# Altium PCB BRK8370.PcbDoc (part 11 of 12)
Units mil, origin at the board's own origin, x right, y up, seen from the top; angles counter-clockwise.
Board outline 8267.72 x 5708.66 mil, 6 copper layers (L1-TOP, L2-GND, L3-PWR, L4-PWR, L5-GND, L6-BOT), stack 68.606 mil thick; 319 components, 516 nets, 2008 pads, 1743 vias.
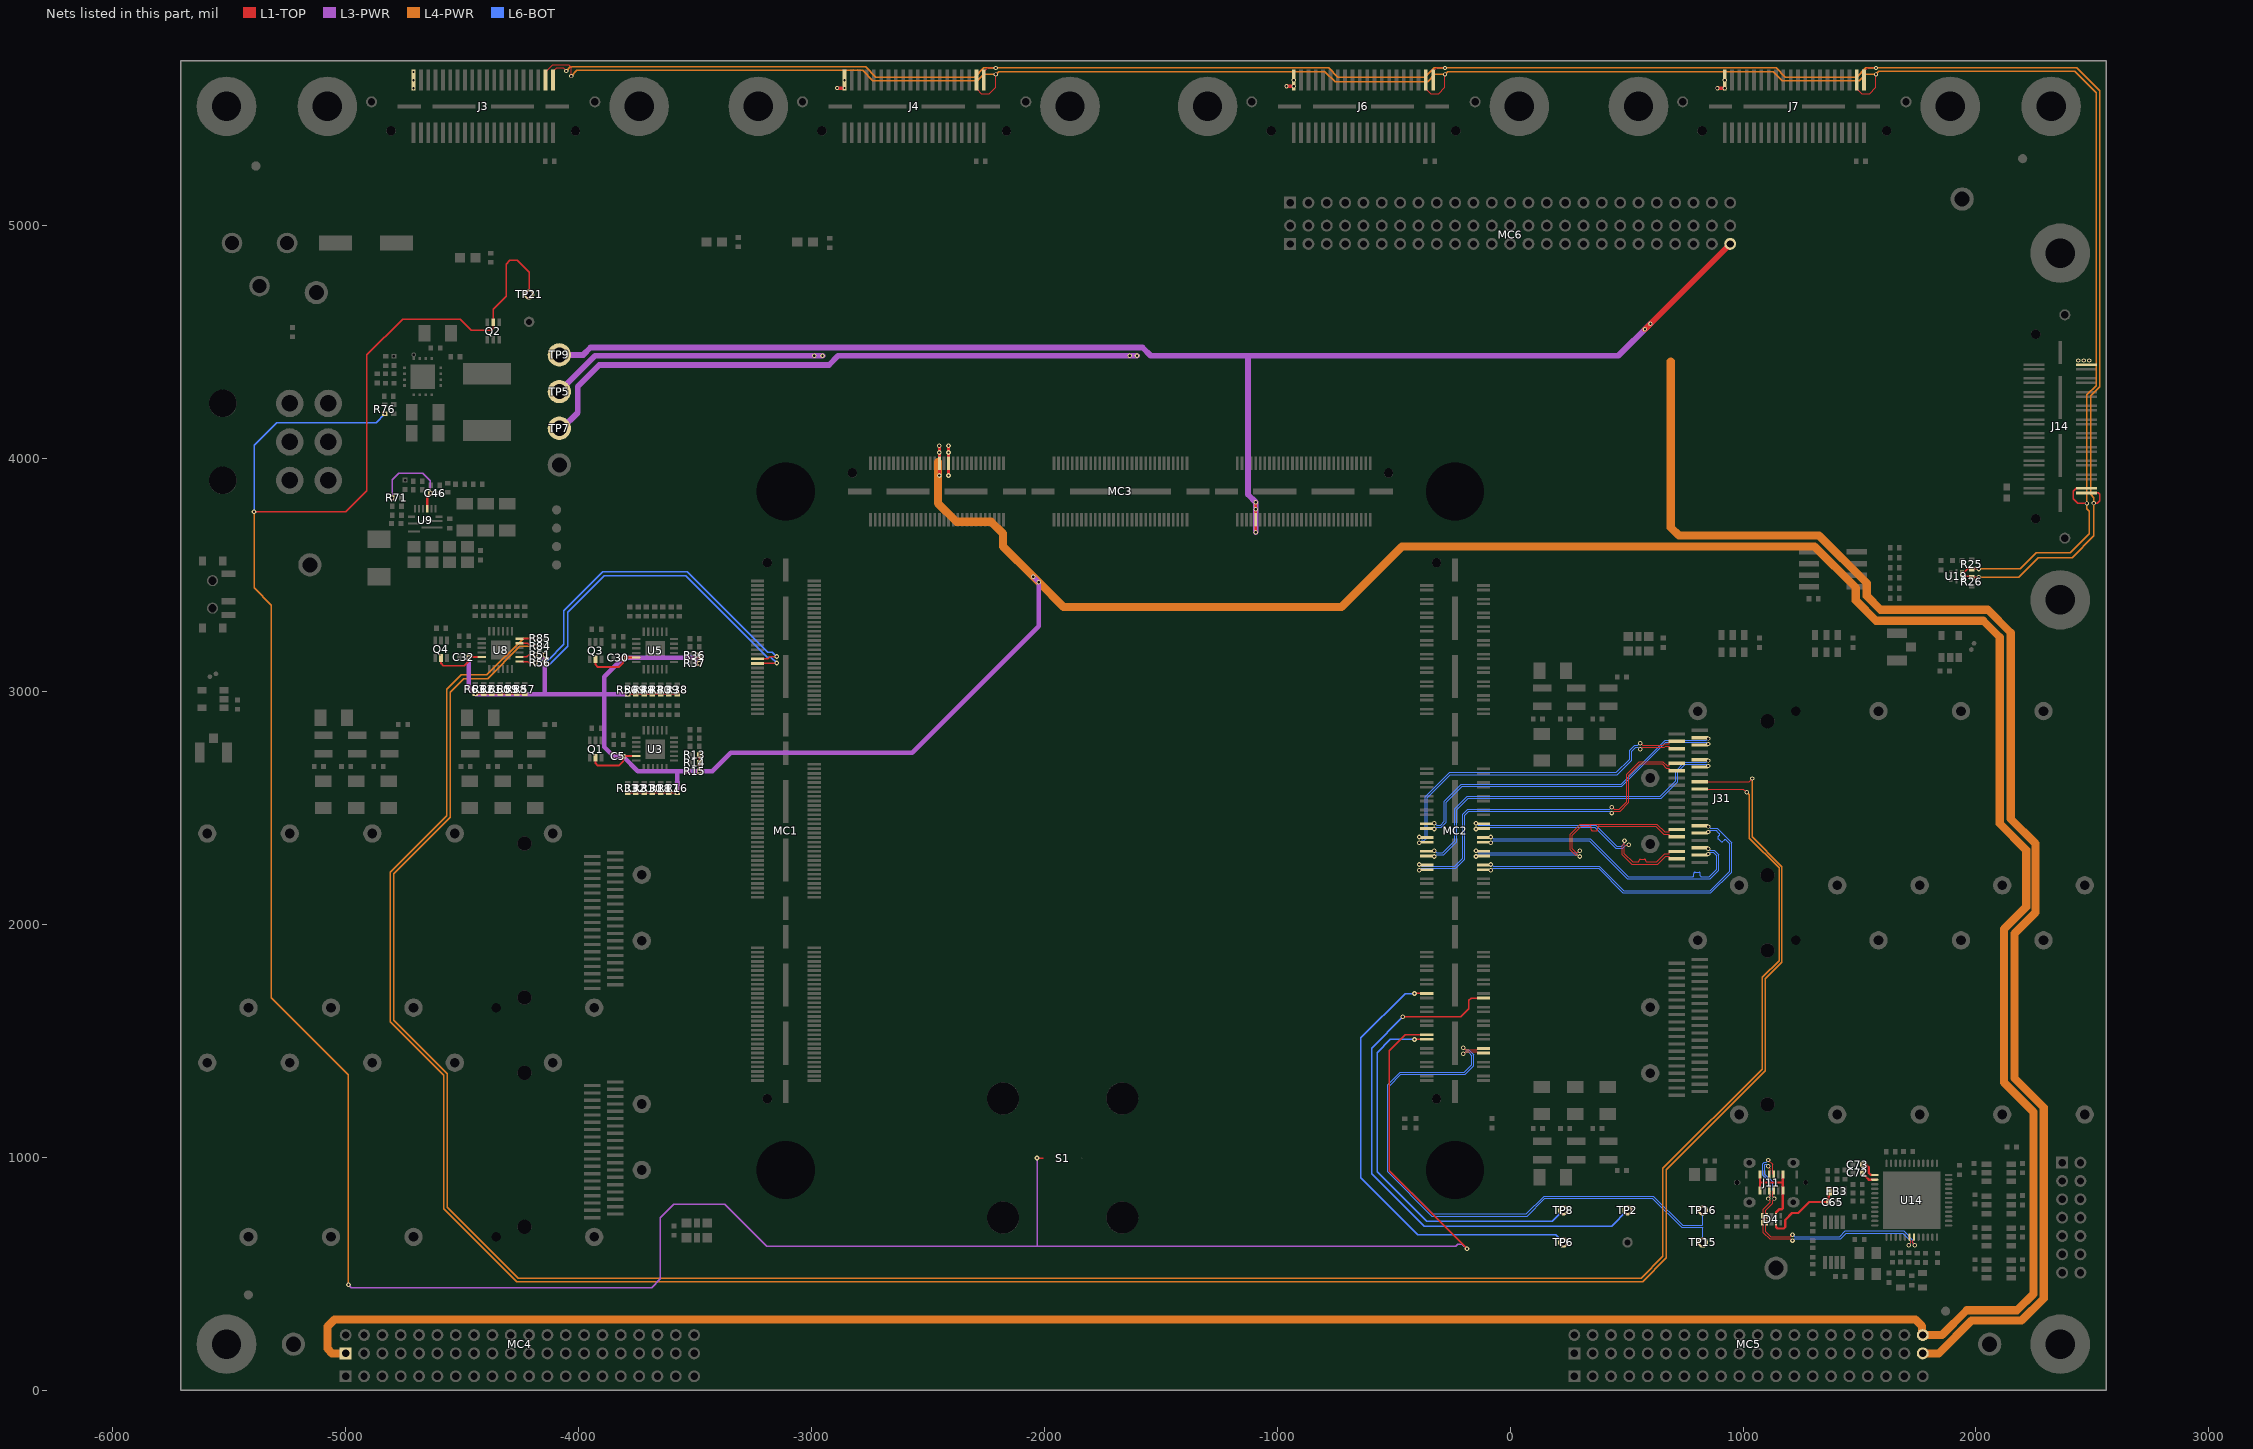
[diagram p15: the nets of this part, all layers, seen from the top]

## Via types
v1: diameter 20, hole 10, L1-TOP to L6-BOT, tented both sides, 957 vias
v2: diameter 18, hole 10, L1-TOP to L6-BOT, tented both sides, 786 vias

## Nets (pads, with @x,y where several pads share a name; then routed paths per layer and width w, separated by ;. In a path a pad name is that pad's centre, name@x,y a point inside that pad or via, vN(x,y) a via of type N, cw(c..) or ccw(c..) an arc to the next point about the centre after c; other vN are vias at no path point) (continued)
QSFP_4_RX1_N: J31.18 MC2.63 | length 1383.8
  L6-BOT w3.3: v1(-325.98,2433.76) -323.7,2433.76 -315.7,2425.76 -298.75,2425.76 -282.34,2442.17 -282.34,2528 -209.66,2600.68 -61.42,2600.68 476.12,2600.68 665.38,2789.93 841.14,2789.93 848.29,2797.08 v2(850.43,2797.08)
QSFP_4_RX1_P: J31.17 MC2.61 | length 1383.8
  L6-BOT w3.3: v1(-325.98,2408.76) -323.7,2408.76 -315.7,2416.76 -295.02,2416.76 -273.34,2438.44 -273.34,2524.27 -205.93,2591.68 -61.42,2591.68 479.85,2591.68 669.11,2780.93 841.14,2780.93 848.29,2773.79 v2(850.43,2773.79)
QSFP_4_RX2_N: J31.21 MC2.59 | length 1414.4
  L1-TOP w3.3: v1(559.06,2776.97) 561.34,2776.97 569.34,2768.97 658.19,2768.97 663.41,2774.18 680.43,2774.18 682.36,2776.12 682.36,2780.19 687.6,2785.43 J31.21@716.14,2785.43
  L6-BOT w3.3: v1(-389.76,2374.7) -387.48,2374.7 -379.48,2366.7 -374.22,2366.7 -365.02,2375.91 -365.02,2546.94 -260.1,2651.86 -61.42,2651.86 456.6,2651.86 512.94,2708.2 512.94,2746.73 535.18,2768.97 548.77,2768.97 556.77,2776.97 v1(559.06,2776.97)
QSFP_4_RX2_P: J31.22 MC2.57 | length 1414.4
  L1-TOP w3.3: v1(559.06,2751.97) 561.34,2751.97 569.34,2759.97 661.92,2759.97 667.14,2765.18 680.43,2765.18 682.36,2763.25 682.36,2759.18 687.6,2753.94 J31.22@716.14,2753.94
  L6-BOT w3.3: v1(-389.76,2349.7) -387.48,2349.7 -379.48,2357.7 -370.49,2357.7 -356.02,2372.18 -356.02,2543.21 -256.37,2642.86 -61.42,2642.86 460.33,2642.86 521.94,2704.47 521.94,2743 538.9,2759.97 548.77,2759.97 556.77,2751.97 v1(559.06,2751.97)
QSFP_4_RX3_N: J31.15 MC2.55 | length 1448.2
  L6-BOT w3.3: v1(-325.98,2315.65) -323.7,2315.65 -315.7,2307.65 -289.18,2307.65 -238.47,2358.36 -238.47,2495.6 -184.01,2550.06 -61.42,2550.06 644.41,2550.06 710.35,2616 710.35,2657.74 748.06,2695.44 841.14,2695.44 848.29,2702.59 v2(850.43,2702.59)
QSFP_4_RX3_P: J31.14 MC2.53 | length 1448.2
  L6-BOT w3.3: v1(-325.98,2290.65) -323.7,2290.65 -315.7,2298.65 -285.46,2298.65 -229.47,2354.63 -229.47,2491.87 -180.28,2541.06 -61.42,2541.06 648.13,2541.06 719.35,2612.27 719.35,2654.01 751.78,2686.44 841.14,2686.44 848.29,2679.3 v2(850.43,2679.3)
QSFP_4_RX4_N: J31.24 MC2.51 | length 1495.6
  L1-TOP w3.3: v1(437.01,2502.38) 439.29,2502.38 447.29,2494.38 468.41,2494.38 500.93,2526.9 500.93,2643.71 554.91,2697.69 656.14,2697.69 674.14,2679.7 680.43,2679.7 682.36,2681.63 682.36,2685.7 687.6,2690.94 J31.24@716.14,2690.94
  L6-BOT w3.3: v1(-389.76,2256.59) -387.48,2256.59 -379.48,2248.59 -238,2248.59 -203.6,2283 -203.6,2472.14 -181.36,2494.38 -61.42,2494.38 426.72,2494.38 434.72,2502.38 v1(437.01,2502.38)
QSFP_4_RX4_P: J31.25 MC2.49 | length 1495.6
  L1-TOP w3.3: v1(437.01,2477.38) 439.29,2477.38 447.29,2485.38 472.14,2485.38 509.93,2523.17 509.93,2639.98 558.64,2688.69 652.42,2688.69 670.41,2670.7 680.43,2670.7 682.36,2668.76 682.36,2664.69 687.6,2659.45 J31.25@716.14,2659.45
  L6-BOT w3.3: v1(-389.76,2231.59) -387.48,2231.59 -379.48,2239.59 -234.28,2239.59 -194.6,2279.27 -194.6,2468.41 -177.63,2485.38 -61.42,2485.38 426.72,2485.38 434.72,2477.38 v1(437.01,2477.38)
QSFP_4_SCL_3V3: J31.11 R84.1 U8.11 | length 10777.5
  L1-TOP w5: J31.11@814.96,2580.71 1001.97,2580.71 v2(1015.75,2566.93)
  L1-TOP w6: U8.11@-4253.94,3206.69 -4218.5,3206.69 -4204.72,3192.91 v1(-4185.04,3192.91)
  L4-PWR w6: v1(-4185.04,3192.91) -4251.97,3192.91 -4389.76,3055.12 -4492.13,3055.12 -4551.25,2995.99 -4551.25,2458.99 -4793.47,2216.78 -4793.47,1588.38 -4563.71,1358.62 -4563.71,785.27 -4259.09,480.64 563.32,480.64 656.19,573.51 656.19,951.56 1082.68,1378.05 1082.68,1771.7 1155.12,1844.15 1155.12,2242.52 1027.56,2370.08 1027.56,2555.12 v2(1015.75,2566.93)
QSFP_4_SCL_VIO: MC1.145 R51.1 U8.8 | length 1597.2
  L1-TOP w6: U8.8@-4253.94,3147.64 -4222.44,3147.64 -4212.6,3157.48 v1(-4185.04,3157.48) ; MC1.145@-3231.89,3139.76 -3187.01,3139.76 -3177.17,3149.61 v1(-3149.61,3149.61)
  L6-BOT w6: v1(-4185.04,3157.48) -4161.42,3133.86 -4130.95,3133.86 -4062.99,3201.81 -4062.99,3347.08 -3897.06,3513.01 -3532.7,3513.01 -3188.35,3168.66 -3168.66,3168.66 v1(-3149.61,3149.61)
QSFP_4_SDA_3V3: J31.12 R85.1 U8.12 | length 10936
  L1-TOP w5: J31.12@814.96,2612.2 1026.28,2612.2 1039.37,2625.3 v2(1039.37,2625.98)
  L1-TOP w6: U8.12@-4253.94,3226.38 -4187.01,3226.38 v1(-4185.04,3228.35)
  L4-PWR w6: v1(-4185.04,3228.35) -4236.22,3228.35 -4393.7,3070.87 -4503.54,3070.87 -4566.28,3008.13 -4566.28,2465.22 -4808.49,2223 -4808.49,1582.15 -4578.74,1352.4 -4578.74,779.04 -4265.31,465.61 569.54,465.61 671.21,567.28 671.21,945.67 1096.48,1370.93 1096.48,1766.25 1166.93,1836.7 1166.93,2247.41 1039.37,2374.97 v2(1039.37,2625.98)
QSFP_4_SDA_VIO: MC1.143 R56.1 U8.7 | length 1597
  L1-TOP w6: U8.7@-4253.94,3127.95 -4218.5,3127.95 -4212.6,3122.05 v1(-4185.04,3122.05) ; MC1.143@-3231.89,3120.08 -3230.91,3121.06 -3150.59,3121.06 v1(-3149.61,3122.05)
  L6-BOT w6: v1(-4185.04,3122.05) -4173.23,3110.24 -4129.92,3110.24 -4047.24,3192.91 -4047.24,3340.56 -3890.54,3497.27 -3539.22,3497.27 -3188.96,3147.01 -3174.57,3147.01 v1(-3149.61,3122.05)
QSFP_4_TX1_N: J31.37 MC2.64 | length 1030.6
  L1-TOP w3.3: v1(491.12,2359.27) 489.51,2357.66 489.51,2346.35 482,2338.84 482,2298.96 522.23,2258.73 633.12,2258.73 667.14,2292.74 680.43,2292.74 682.36,2290.81 682.36,2286.74 687.6,2281.5 J31.37@716.14,2281.5
  L6-BOT w3.3: v1(-146.46,2433.76) -144.17,2433.76 -136.17,2425.76 -61.42,2425.76 368.09,2425.76 458.09,2335.75 478.91,2335.75 489.51,2346.35 489.51,2357.66 v1(491.12,2359.27)
QSFP_4_TX1_P: J31.36 MC2.62 | length 1030.6
  L1-TOP w3.3: v1(508.8,2341.6) 507.18,2339.98 495.87,2339.98 491,2335.11 491,2302.68 525.95,2267.73 533.62,2267.73 548.25,2267.73 ccw(c548.25,2273.39) 553.91,2273.39 553.91,2274.38 cw(c559.57,2274.38) 559.57,2280.04 576.55,2280.04 cw(c576.55,2274.38) 582.21,2274.38 582.21,2273.39 ccw(c587.87,2273.39) 587.87,2267.73 617.82,2267.73 629.39,2267.73 663.41,2301.74 680.43,2301.74 682.36,2303.68 682.36,2307.75 687.6,2312.99 J31.36@716.14,2312.99
  L6-BOT w3.3: v1(-146.46,2408.76) -144.17,2408.76 -136.17,2416.76 -61.42,2416.76 364.36,2416.76 454.37,2326.75 482.64,2326.75 495.87,2339.98 507.18,2339.98 v1(508.8,2341.6)
QSFP_4_TX2_N: J31.2 MC2.60 | length 1187.5
  L6-BOT w3.3: v1(-82.68,2374.7) -80.39,2374.7 -72.39,2366.7 -61.42,2366.7 344.3,2366.7 507.41,2203.6 781.37,2203.6 783.02,2203.6 ccw(c783.02,2209.26) 788.68,2209.26 788.68,2217.71 cw(c794.34,2217.71) 794.34,2223.37 811.32,2223.37 cw(c811.32,2217.71) 816.98,2217.71 816.98,2209.26 ccw(c822.64,2209.26) 822.64,2203.6 842.52,2203.6 854.8,2203.6 886.95,2235.75 886.95,2294.15 872.61,2308.49 859.71,2308.49 852.56,2301.35 v2(850.43,2301.35)
QSFP_4_TX2_P: J31.3 MC2.58 | length 1187.5
  L6-BOT w3.3: v1(-82.68,2349.7) -80.39,2349.7 -72.39,2357.7 -61.42,2357.7 340.57,2357.7 503.68,2194.6 858.52,2194.6 895.95,2232.03 895.95,2297.88 876.34,2317.49 859.71,2317.49 852.56,2324.64 v2(850.43,2324.64)
QSFP_4_TX3_N: J31.34 MC2.56 | length 1069.3
  L1-TOP w3.3: v1(299.21,2315.65) 296.93,2315.65 288.93,2307.65 283.67,2307.65 266.59,2324.72 266.59,2382.36 305.21,2420.98 312.57,2420.98 342.52,2420.98 cw(c342.52,2415.32) 348.18,2415.32 348.18,2406.87 ccw(c353.84,2406.87) 353.84,2401.21 370.82,2401.21 ccw(c370.82,2406.87) 376.48,2406.87 376.48,2415.32 cw(c382.14,2415.32) 382.14,2420.98 429.8,2420.98 625.73,2420.98 659.47,2387.23 680.43,2387.23 682.36,2385.3 682.36,2381.22 687.6,2375.98 J31.34@716.14,2375.98
  L6-BOT w3.3: v1(-146.46,2315.65) -144.17,2315.65 -136.17,2307.65 -61.42,2307.65 288.93,2307.65 296.93,2315.65 v1(299.21,2315.65)
QSFP_4_TX3_P: J31.33 MC2.54 | length 1069.3
  L1-TOP w3.3: v1(299.21,2290.65) 296.93,2290.65 288.93,2298.65 279.94,2298.65 257.59,2321 257.59,2386.08 301.49,2429.98 629.45,2429.98 663.2,2396.23 680.43,2396.23 682.36,2398.17 682.36,2402.24 687.6,2407.48 J31.33@716.14,2407.48
  L6-BOT w3.3: v1(-146.46,2290.65) -144.17,2290.65 -136.17,2298.65 -61.42,2298.65 288.93,2298.65 296.93,2290.65 v1(299.21,2290.65)
QSFP_4_TX4_N: J31.5 MC2.52 | length 1371.9
  L6-BOT w3.3: v1(-82.68,2256.59) -80.39,2256.59 -72.39,2248.59 -61.42,2248.59 383.67,2248.59 487.72,2144.54 858.73,2144.54 942.07,2227.88 942.07,2346.2 928.1,2360.17 926.93,2361.34 ccw(c922.93,2357.34) 918.93,2361.34 912.95,2355.36 cw(c908.95,2359.37) 904.95,2355.36 892.94,2367.37 cw(c896.94,2371.37) 892.94,2375.37 898.92,2381.35 ccw(c894.91,2385.35) 898.92,2389.35 890.06,2398.21 885.29,2402.98 859.71,2402.98 852.56,2395.83 v2(850.43,2395.83)
QSFP_4_TX4_P: J31.6 MC2.50 | length 1371.9
  L6-BOT w3.3: v1(-82.68,2231.59) -80.39,2231.59 -72.39,2239.59 -61.42,2239.59 379.94,2239.59 484,2135.54 862.46,2135.54 951.07,2224.15 951.07,2349.93 889.02,2411.98 859.71,2411.98 852.56,2419.13 v2(850.43,2419.13)
RT6278_VCC: C46.2 R71.2 U9.9 | length 391.9
  L1-TOP w9: U9.9@-4649.76,3784.66 -4649.76,3836.64 v1(-4636.03,3850.36)
  L3-PWR w6: v1(-4799.88,3830.94) -4799.88,3908.78 -4771.65,3937.01 -4669.29,3937.01 -4636.03,3903.75 v1(-4636.03,3850.36)
SZG_SCL_3V3: J3.1 J4.1 J6.1 J7.1 J14.1@2475.2,3851.92 R26.1 U19.6 | length 9809.9
  L1-TOP w5: J3.1@-4110.2,5624.61 -4110.2,5661.36 -4094.54,5677.02 -4066.39,5677.02 v2(-4052.88,5663.52) ; J4.1@-2259.81,5624.61 -2259.81,5661.36 -2244.14,5677.02 v2(-2208.86,5677.02) ; J6.1@-330.62,5624.61 -330.67,5661.36 -315.01,5677.02 v2(-279.72,5677.02) ; J7.1@1519.72,5624.61 1519.72,5661.36 1535.38,5677.02 v2(1570.67,5677.02)
  L1-TOP w6: U19.6@1940.16,3494.09 1979.13,3494.09 R26.1@1983.07,3490.16 v1(2011.81,3490.16) ; J14.1@2475.2,3851.92 2526.03,3851.92 2531.5,3846.46 2531.5,3818.9 2520.81,3808.22 v2(2506.3,3808.22)
  L4-PWR w6: v2(-4052.88,5663.52) -4035.3,5681.1 -2767.72,5681.1 -2724.41,5637.8 -2299.21,5637.8 -2259.99,5677.02 v2(-2208.86,5677.02) -779.38,5677.02 -740.16,5637.8 -366.14,5637.8 -326.92,5677.02 v2(-279.72,5677.02) 1141.88,5677.02 1181.1,5637.8 1488.19,5637.8 1527.42,5677.02 v2(1570.67,5677.02) 2433.64,5677.02 2531.5,5579.16 2531.5,4307.09 2493.22,4268.81 2493.22,3845.36 2506.3,3832.28 v2(2506.3,3808.22) 2506.3,3667.72 2413.39,3574.8 2267.72,3574.8 2183.07,3490.16 v1(2011.81,3490.16)
SZG_SDA_3V3: J3.3 J4.3 J6.3 J7.3 J14.3 R25.1 U19.7 | length 10176.8
  L1-TOP w4.4: J3.3@-4141.65,5624.61 -4141.65,5661.36 -4111.55,5691.46 -4041.86,5691.46 -4031.5,5681.1 v2(-4031.5,5641.73)
  L1-TOP w5: J4.3@-2291.31,5624.61 -2291.31,5587.86 -2270.37,5566.93 -2236.27,5566.93 -2208.86,5594.34 v2(-2208.86,5649.46) ; J6.3@-362.12,5624.61 -362.17,5587.86 -341.24,5566.93 -307.14,5566.93 -279.72,5594.34 v2(-279.72,5649.46) ; J7.3@1488.22,5624.61 1488.22,5587.86 1509.15,5566.93 1543.26,5566.93 1570.67,5594.34 v2(1570.67,5649.46)
  L1-TOP w6: U19.7@1940.16,3513.78 1952.76,3513.78 1964.57,3525.59 R25.1@1983.07,3525.59 v1(2011.81,3525.59) ; J14.3@2475.2,3871.6 2430.51,3871.6 2417.32,3858.41 2417.32,3826.77 2437.01,3807.09 v2(2476.38,3807.09)
  L4-PWR w6: v2(-4031.5,5641.73) -4007.23,5666 -2780.17,5666 -2736.22,5622.05 -2287.4,5622.05 -2259.99,5649.46 v2(-2208.86,5649.46) -2196.9,5661.42 -795.28,5661.42 -751.97,5618.11 -354.33,5618.11 -322.98,5649.46 v2(-279.72,5649.46) -267.77,5661.42 1129.92,5661.42 1169.29,5622.05 1500,5622.05 1527.42,5649.46 v2(1570.67,5649.46) 1583.72,5662.51 2424.53,5662.51 2515.75,5571.29 2515.75,4313.2 2476.38,4273.83 v2(2476.38,3807.09) 2476.38,3794.99 2476.38,3783.46 2487,3772.85 2487,3675.97 2405.51,3594.49 2259.84,3594.49 2190.95,3525.59 v1(2011.81,3525.59)
USB_DN: D4.5 D4.6 J11.A7 J11.B7 U14.6 | length 1213.9
  L1-TOP w4: v2(1108.73,987.57) 1127.05,969.25 1127.05,942.47 1127.98,941.53 1127.98,928.91 J11.B7@1131.89,925 ; J11.A7@1112.2,856.89 1116.11,852.98 1116.11,840.36 1117.05,839.42 1117.05,831.34 1109.39,823.68 1108.73,823.68 1108.73,820.66 1116.73,812.66 1116.73,806.35 1087.52,777.14 1087.52,760.94 1082.68,756.1 1082.68,741.34 1087.5,736.51 1087.52,730.42 1082.68,725.59 1082.68,710.83 1087.52,705.98 1087.52,676.18 1114.47,649.23 1202.26,649.23 1209.76,641.73 v1(1212.6,641.73) ; v1(1711.82,621.87) 1711.82,624.71 1719.41,632.3 1719.41,640.4 1714.57,645.25 U14.6@1714.57,656.5
  L6-BOT w4: v2(1108.73,822) 1108.73,823.34 1116.73,831.34 1116.73,889.48 1083.67,922.54 1083.67,970.87 1091.87,979.07 1099.38,979.07 1107.88,987.57 v2(1108.73,987.57) ; v1(1212.6,641.73) 1215.44,641.73 1222.94,649.23 1420.06,649.23 1444.16,673.33 1685.82,673.33 1719.32,639.83 1719.32,632.21 1711.82,624.71 v1(1711.82,621.87)
USB_DP: D4.4 D4.7 J11.A6 J11.B6 U14.7 | length 1165.4
  L1-TOP w4: v2(1108.73,960.57) 1108.73,959.54 1117.05,951.22 1117.05,942.47 1116.11,941.53 1116.11,928.91 J11.B6@1112.2,925 ; J11.A6@1131.89,856.89 1127.98,852.98 1127.98,840.36 1127.05,839.42 1127.05,831.34 1134.73,823.66 1134.73,820.66 1126.73,812.66 1126.73,802.21 1097.52,773 1097.52,760.94 1102.36,756.1 1102.36,741.34 1097.54,736.51 1097.52,730.42 1102.36,725.59 1102.36,710.83 1097.52,705.98 1097.52,680.32 1118.61,659.23 1202.26,659.23 1209.76,666.73 v1(1212.6,666.73) ; U14.7@1734.25,656.5 1734.25,645.25 1729.41,640.4 1729.41,632.21 1736.82,624.8 v1(1736.82,621.87)
  L6-BOT w4: v2(1108.73,960.57) 1107.88,960.57 1099.38,969.07 1096.01,969.07 1093.67,966.72 1093.67,926.68 1126.73,893.63 1126.73,831.34 1134.73,823.34 v2(1134.73,822) ; v1(1212.6,666.73) 1215.44,666.73 1222.94,659.23 1415.92,659.23 1440.01,683.33 1689.96,683.33 1729.32,643.97 1729.32,632.21 1736.82,624.71 v1(1736.82,621.87)
VBATT: MC2.13 TP8.1 | length 1654.9
  L1-TOP w6: v1(-410.77,1505.26) -410.44,1505.58 -358.2,1505.58 MC2.13@-357.87,1505.91
  L6-BOT w6: v1(-410.77,1505.26) -514.43,1505.26 -570.87,1448.82 -570.87,937.03 -358.75,724.92 181.61,724.92 TP8.1@228.35,771.65
VBUS_C: C65.2 D4.2 D4.9 FB3.2 J11.A4 J11.A9 J11.B4 J11.B9 | length 751.2
  L1-TOP w10: J11.A9@1072.83,856.89 1072.83,891.33 ; J11.B4@1072.83,925 1072.83,891.33 ; J11.B9@1171.26,925 1171.26,890.94 ; FB3.2@1370.87,854.33 1368.31,851.77 1368.31,809.65 C65.2@1365.75,807.09 1284.43,807.09 1237.18,759.84 1210.85,759.84 1181.24,730.23 1181.24,700.29 1174.45,693.5 1147.99,693.5 1141.73,699.76 D4.9@1141.73,718.21 1141.73,762.93 1154.39,775.59 1165.4,775.59 1171.26,781.45 J11.A4@1171.26,856.89 1171.26,890.94 ; 1072.83,891.33 1170.87,891.33 1171.26,890.94
VCCA: C73.2 U14.37 | length 85.9
  L1-TOP w10: C73.2@1512.2,967.52 1528.54,967.52 1539.37,956.69 1539.37,933.07 1549.21,923.23 U14.37@1565.94,923.23
VCCADC: MC2.26 TP2.1 | length 2348.2
  L1-TOP w6: v1(-460.63,1602.36) -212.6,1602.36 -177.17,1637.8 -177.17,1673.23 -167.32,1683.07 MC2.26@-114.57,1683.07
  L6-BOT w6: v1(-460.63,1602.36) -594.49,1468.5 -594.49,929.49 -369.28,704.28 436.57,704.28 TP2.1@503.94,771.65
VCCO_64_66: J6.39 J7.39 J14.39 MC3.35 MC5.39 TP7.1 | length 8867.5
  L1-TOP w12: v1(-2411.42,3927.17) MC3.35@-2411.42,3979.92 v1(-2411.42,4025.59) v1(-2411.42,4055.12)
  L1-TOP w15: v2(-960.63,5598.43) v2(-929.13,5598.43) ; v2(889.78,5589.61) v2(921.27,5589.61)
  L3-PWR w25: TP7.1@-4082.68,4129.92 -4070.87,4129.92 -4003.94,4196.85 -4003.94,4309 -3911.36,4401.57 -2925.2,4401.57 -2885.83,4440.94 v1(-1633.86,4440.94) v1(-1602.36,4440.94)
  L4-PWR w35: 689.56,4416.79 689.56,3704.14 724.41,3669.29 1326.65,3669.29 1531.5,3464.45 1531.5,3409.33 1590.44,3350.39 2051.07,3350.39 2149.61,3251.85 2149.61,2452.76 2255.91,2346.46 2255.91,2051.18 2165.35,1960.63 2165.35,1338.58 2291.31,1212.62 2291.31,393.74 2195.55,297.98 1980.77,297.98 1840.27,157.48 MC5.39@1771.65,157.48
  other v2: 2439.85,4420.86 2462.85,4420.86 2486.85,4420.86 -929.12,5624.61 921.27,5624.61
VCCO_67_68_69: C5.2 C30.2 C32.2 J3.39 J4.39 MC3.31 MC4.1 MC5.40 Q1.5 Q3.5 Q4.5 R13.2 R14.2 R15.2 R16.2 R17.2 R18.2 R30.2 R31.2 R32.2 R33.2 R36.2 R37.2 R38.2 R39.2 R40.2 R41.2 R48.2 R49.2 R50.2 R51.2 R56.2 R57.2 R58.2 R59.2 R60.2 R61.2 R62.2 R63.2 TP5.1 U3.23 U5.23 U8.23 | length 22910
  L1-TOP w6: v1(-4442.91,2990.16) R62.2@-4407.48,2990.16 R61.2@-4372.05,2990.16 R60.2@-4336.61,2990.16 R59.2@-4301.18,2990.16 R58.2@-4265.75,2990.16 R57.2@-4230.31,2990.16 ; R56.2@-4145.67,3122.05 v1(-4145.67,3157.48) ; R33.2@-3789.37,2564.96 R32.2@-3753.94,2564.96 R31.2@-3718.5,2564.96 R30.2@-3683.07,2564.96 R18.2@-3647.64,2564.96 R17.2@-3612.2,2564.96 v1(-3576.77,2564.96) ; v1(-3789.37,2988.19) R49.2@-3753.94,2988.19 R48.2@-3718.5,2988.19 R41.2@-3683.07,2988.19 R40.2@-3647.64,2988.19 R39.2@-3612.2,2988.19 R38.2@-3576.77,2988.19 ; v1(-3482.28,2657.48) R14.2@-3482.28,2692.91 R13.2@-3482.28,2728.35 ; v1(-3482.28,3120.08) R36.2@-3482.28,3155.51
  L1-TOP w8: Q4.5@-4590.55,3143.7 -4590.55,3120.08 -4580.71,3110.24 -4490.16,3110.24 -4472.05,3128.35 v1(-4472.05,3145.67) ; C32.2@-4472.05,3149.61 v1(-4472.05,3145.67) ; U8.23@-4415.35,3147.64 -4416.08,3146.91 -4470.8,3146.91 v1(-4472.05,3145.67) ; Q1.5@-3927.17,2714.57 -3927.17,2690.94 -3917.32,2681.1 -3826.77,2681.1 -3808.66,2699.21 v1(-3808.66,2720.47) -3807.42,2721.72 -3752.69,2721.72 U3.23@-3751.97,2722.44 ; Q3.5@-3927.17,3137.8 -3927.17,3114.17 -3917.32,3104.33 -3826.77,3104.33 -3808.66,3122.44 v1(-3808.66,3143.7) -3807.42,3144.94 -3752.69,3144.94 U5.23@-3751.97,3145.67
  L1-TOP w12: v1(-2450.79,3927.17) MC3.31@-2450.79,3979.92 v1(-2450.79,4025.59) v1(-2450.79,4055.12)
  L1-TOP w15: v2(-2889.76,5590.55) v2(-2858.27,5590.55)
  L3-PWR w20: v1(-4472.05,3145.67) -4472.05,3019.29 v1(-4442.91,2990.16) -4440.94,2988.19 -4145.67,2988.19 ; v1(-4145.67,3157.48) -4145.67,2988.19 ; v1(-3789.37,2988.19) -3889.76,2988.19 ; v1(-3576.77,2564.96) -3576.77,2655.51 -3574.8,2657.48 ; v1(-3482.28,3120.08) -3505.91,3143.7 v1(-3808.66,3143.7) -3889.76,3062.6 -3889.76,2988.19 ; v1(-2047.24,3492.13) v1(-2023.62,3468.5) -2023.62,3279.43 -2566.83,2736.22 -3346.46,2736.22 -3425.2,2657.48 v1(-3482.28,2657.48) -3574.8,2657.48 ; -4145.67,2988.19 -3889.76,2988.19 ; -3889.76,2988.19 -3889.76,2761.26 -3848.98,2720.47 v1(-3808.66,2720.47) -3745.67,2657.48 -3574.8,2657.48
  L3-PWR w25: TP5.1@-4082.68,4287.4 -3929.13,4440.94 v1(-2988.19,4440.94) v1(-2952.76,4440.94)
  L4-PWR w35: MC4.1@-5000,157.48 -5058.24,157.48 -5078.74,177.98 -5078.74,272.48 -5048.79,302.43 1740.88,302.43 1769.15,274.16 1769.15,238.72 MC5.40@1771.65,236.22 1854.3,236.22 1960.6,342.52 2177.1,342.52 2246.77,412.19 2246.77,1194.17 2120.81,1320.13 2120.81,1979.08 2215.91,2074.17 2215.91,2319.53 2102.36,2433.07 2102.36,3232.28 2031.5,3303.15 1570.87,3303.15 1484.25,3389.76 1484.25,3444.88 1306.32,3622.81 -463.8,3622.81 -724.41,3362.2 -1917.32,3362.2 v1(-2023.62,3468.5) v1(-2047.24,3492.13) -2177.17,3622.05 -2177.17,3677.17 -2228.35,3728.35 -2377.72,3728.35 -2456.92,3807.54 -2456.92,3984.25
  other v2: -4708.65,5589.61 -4708.65,5624.61 -2858.26,5624.61 -4708.65,5659.61
VCCO_88_89: MC3.130 MC6.49 TP9.1 | length 6186.5
  L1-TOP w12: v1(-1092.52,3683.86) MC3.130@-1092.52,3736.61 v1(-1092.52,3782.28) v1(-1092.52,3811.81)
  L1-TOP w25: v1(578.74,4555.12) v1(602.36,4578.74) MC6.49@944.88,4921.26
  L3-PWR w25: TP9.1@-4082.68,4444.88 -3980.31,4444.88 -3948.82,4476.38 -1578.74,4476.38 -1543.31,4440.94 -1125.98,4440.94 ; v1(-1092.52,3683.86) v1(-1092.52,3782.28) v1(-1092.52,3811.81) -1125.98,3845.28 -1125.98,4440.94 ; v1(602.36,4578.74) 464.57,4440.94 -1125.98,4440.94
VCORE: C72.2 U14.38 | length 65.9
  L1-TOP w10: C72.2@1512.2,932.09 1512.2,931.5 1540.16,903.54 U14.38@1565.94,903.54
VREFP: MC2.27 TP6.1 | length 1948.7
  L1-TOP w6: v1(-410.44,1702.43) -410.12,1702.76 MC2.27@-357.87,1702.76 MC2.27@-357.55,1703.08
  L6-BOT w6: v1(-410.44,1702.43) -451.11,1702.43 -641.31,1512.23 -641.31,910.62 -396.65,665.96 196.24,665.96 TP6.1@228.35,633.86
XADC_VN_C: MC2.12 TP16.1 | length 2527
  L1-TOP w3.3: v1(-200.79,1469.19) -198.5,1469.19 -190.5,1461.19 -142.55,1461.19 -137.2,1466.54 MC2.12@-114.57,1466.54
  L6-BOT w3.3: v1(-200.79,1469.19) -198.5,1469.19 -190.5,1461.19 -177.08,1461.19 -155.23,1439.34 -155.23,1393.44 -193.22,1355.46 -433.07,1355.46 -468.97,1355.46 -516.87,1307.55 -516.87,940.48 -332.61,756.22 68.83,756.22 145.57,832.96 614.43,832.96 740.13,707.26 824.84,707.26 826.77,709.19 TP16.1@826.77,771.65
XADC_VP_C: MC2.10 TP15.1 | length 2527
  L1-TOP w3.3: v1(-200.79,1444.19) -198.5,1444.19 -190.5,1452.19 -142.55,1452.19 -137.2,1446.85 MC2.10@-114.57,1446.85
  L6-BOT w3.3: v1(-200.79,1444.19) -198.5,1444.19 -190.5,1452.19 -180.81,1452.19 -164.23,1435.61 -164.23,1397.17 -196.95,1364.46 -433.07,1364.46 -472.7,1364.46 -525.87,1311.28 -525.87,936.75 -336.34,747.22 72.56,747.22 149.3,823.96 610.7,823.96 736.41,698.26 824.84,698.26 826.77,696.32 TP15.1@826.77,633.86
XEM8370_PGOOD: MC2.15 Q2.2 R76.2 S1.1 TP21.1 | length 13426.8
  L1-TOP w6: v1(-5393.7,3771.65) -5000,3771.65 -4909.45,3862.2 -4909.45,4444.88 -4755.91,4598.43 -4507.87,4598.43 -4460.63,4551.18 -4374.02,4551.18 -4366.14,4559.06 Q2.2@-4366.14,4584.65 -4366.14,4641.73 -4311.02,4696.85 -4311.02,4834.65 -4295.28,4850.39 -4263.78,4850.39 -4212.6,4799.21 TP21.1@-4212.6,4704.72 ; v1(-2031.5,996.06) S1.1@-2003.94,996.06 ; MC2.15@-357.87,1525.59 -451.07,1525.59 -519.68,1456.98 -519.68,940.94 v1(-185.04,606.3)
  L3-PWR w6: v1(-4988.19,452.76) -4975.57,440.13 -3685.66,440.13 -3648.8,477 -3648.8,740.06 -3590.91,797.95 -3372.94,797.95 -3192.29,617.3 -2031.5,617.3 ; v1(-2031.5,996.06) -2031.5,617.3 ; v1(-185.04,606.3) -204.72,625.98 -224.41,625.98 -233.09,617.3 -2031.5,617.3
  L4-PWR w6: v1(-5393.7,3771.65) -5393.7,3444.88 -5318.9,3370.08 -5318.9,3251.97 -5318.9,1683.69 -4988.19,1352.98 v1(-4988.19,452.76)
  L6-BOT w6: v1(-5393.7,3771.65) -5393.7,4056.99 -5296.55,4154.15 -4869.47,4154.15 v1(-4831.42,4192.2)
pads on no net: FID1.FID? FID2.FID? FID3.FID? FID4.FID? J1.3 J2.0 J3.37 J3.38 J3.MH J3.NC J4.37 J4.38 J4.MH J4.NC J5.12 J5.14 J6.37 J6.38 J6.MH J6.NC J7.37 J7.38 J7.MH J7.NC J8.MH J9.MH J11.A8 J11.B8 J11.M5 J11.M6 J14.1@2362.2,3392.91 J14.1@2362.2,4881.89 J14.37 J14.38 J14.MH J30.MH J31.MH JP3.0 JP3.1 JSO1.1 JSO2.1 JSO3.1 JSO4.1 MC1.55 MC1.56 MC1.159 MC1.MH MC2.9 MC2.11 MC2.19 MC2.23 MC2.25 MC2.69 MC2.70 MC2.71 MC2.72 MC2.73 MC2.74 MC2.75 MC2.76 MC2.77 MC2.78 MC2.79 MC2.80 MC2.81 MC2.82 MC2.83 MC2.84 MC2.85 MC2.86 MC2.87 MC2.88 MC2.89 MC2.90 MC2.91 MC2.92 MC2.93 MC2.94 MC2.95 MC2.96 MC2.97 MC2.98 MC2.99 MC2.100 MC2.117 MC2.119 MC2.MH MC3.30 MC3.32 MC3.132 MC3.133 MC3.135 MC3.MH MH1.1 MH2.1 MH3.1 MH4.1 QSFP1.0 QSFP2.0 QSFP3.0 QSFP4.0 S1.0 U1.2 U3.0 U4.2 U5.0 U5.9 U5.10 U6.2 U7.2 U8.0 U8.9 U8.10 U14.17 U14.18 U14.19 U14.20 U14.21 U14.25 U14.26 U14.27 U14.28 U14.29 U14.30 U14.31 U14.32 U14.33 U18.6 U18.7
copper on no net:
  other v2: -2185.09,5629.92 -255.96,5629.92 1594.44,5629.92

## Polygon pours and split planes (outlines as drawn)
NetC92_2 on L1-TOP "NETC92_2_L01_P597" (solid, pour order 597): 99.2,1052.27 177.94,1052.27 191.72,1066.05 191.72,1192.03 172.03,1211.72 101.17,1211.72 101.17,1155.61 114.94,1141.83 114.94,1107.39 99.2,1091.64
NetC90_2 on L1-TOP "NETC90_2_L01_P598" (solid, pour order 598): 243.88,1052.27 320.65,1052.27 334.43,1066.05 334.43,1192.03 314.75,1211.72 243.88,1211.72 243.88,1155.61 243.88,1093.61
NetC94_2 on L1-TOP "NETC94_2_L01_P599" (solid, pour order 599): 382.66,1052.27 459.43,1052.27 473.21,1066.05 473.21,1192.03 453.53,1211.72 382.66,1211.72 382.66,1155.61 382.66,1093.61
+3.3V_TST on L1-TOP "+3.3V_TST_L01_P600" (solid, pour order 600): 99.2,1020.77 461.4,1020.77 461.4,972.54 475.18,958.76 475.18,898.72 446.64,870.18 197.62,870.18 181.87,885.93 181.87,934.16 157.27,958.76 112.98,958.76 99.2,972.54
+VDCIN on L1-TOP "+VDCIN_L01_P607" (solid, pour order 607): -5283.46,4996.06 -4956.69,4996.06 -4940.94,4980.32 -4940.94,4515.75 -5157.48,4299.21 -5157.48,3834.65 -5181.1,3811.02 -5358.27,3811.02 -5409.45,3862.2 -5409.45,4570.87 -5311.02,4669.29 -5311.02,4968.5
DGND on L1-TOP "DGND_L01_P606" (solid, pour order 606): -4862.2,4984.25 -4862.2,4862.21 -4846.46,4846.46 -4677.17,4846.46 -4661.42,4862.2 -4661.42,4988.19 -4673.23,5000 -4846.46,5000
+VDCIN on L1-TOP "+VDCIN_L01_P605" (solid, pour order 605): -31.5,1417.32 -3.94,1389.76 -3.94,1188.98 -43.31,1149.61 -464.57,1149.61 -484.25,1169.29 -484.25,1393.7 -460.63,1417.32
NetC102_2 on L1-TOP "NETC102_2_L01_P603" (solid, pour order 603): 382.66,2951.67 459.43,2951.67 473.21,2937.89 473.21,2811.91 453.53,2792.22 382.66,2792.22 382.66,2848.32 382.66,2910.33
NetC106_2 on L1-TOP "NETC106_2_L01_P602" (solid, pour order 602): 243.88,2951.67 320.65,2951.67 334.43,2937.89 334.43,2811.91 314.75,2792.22 243.88,2792.22 243.88,2848.32 243.88,2910.33
NetC104_2 on L1-TOP "NETC104_2_L01_P601" (solid, pour order 601): 99.2,2951.67 177.94,2951.67 191.72,2937.89 191.72,2811.91 172.03,2792.22 101.17,2792.22 101.17,2848.32 114.94,2862.1 114.94,2896.55 99.2,2912.3
+3.3V_TST on L1-TOP "+3.3V_TST_L01_P596" (solid, pour order 596): -5134.84,2779.53 -4772.64,2779.53 -4772.64,2827.76 -4758.86,2841.54 -4758.86,2901.57 -4787.4,2930.12 -5036.42,2930.12 -5052.17,2914.37 -5052.17,2866.14 -5076.77,2841.54 -5121.06,2841.54 -5134.84,2827.76
NetC13_2 on L1-TOP "NETC13_2_L01_P595" (solid, pour order 595): -4851.38,2748.03 -4774.61,2748.03 -4760.83,2734.25 -4760.83,2608.27 -4780.51,2588.58 -4851.38,2588.58 -4851.38,2644.68 -4851.38,2706.69
NetC17_2 on L1-TOP "NETC17_2_L01_P594" (solid, pour order 594): -4990.16,2748.03 -4913.39,2748.03 -4899.61,2734.25 -4899.61,2608.27 -4919.29,2588.58 -4990.16,2588.58 -4990.16,2644.68 -4990.16,2706.69
NetC15_2 on L1-TOP "NETC15_2_L01_P593" (solid, pour order 593): -5134.84,2748.03 -5056.1,2748.03 -5042.32,2734.25 -5042.32,2608.27 -5062.01,2588.58 -5132.87,2588.58 -5132.87,2644.68 -5119.09,2658.46 -5119.09,2692.91 -5134.84,2708.66
+3.3V_TST on L1-TOP "+3.3V_TST_L01_P592" (solid, pour order 592): -4504.92,2779.53 -4142.72,2779.53 -4142.72,2827.76 -4128.94,2841.54 -4128.94,2901.57 -4157.48,2930.12 -4406.5,2930.12 -4422.24,2914.37 -4422.24,2866.14 -4446.85,2841.54 -4491.14,2841.54 -4504.92,2827.76
NetC21_2 on L1-TOP "NETC21_2_L01_P591" (solid, pour order 591): -4221.46,2748.03 -4144.69,2748.03 -4130.91,2734.25 -4130.91,2608.27 -4150.59,2588.58 -4221.46,2588.58 -4221.46,2644.68 -4221.46,2706.69
NetC25_2 on L1-TOP "NETC25_2_L01_P590" (solid, pour order 590): -4360.24,2748.03 -4283.46,2748.03 -4269.69,2734.25 -4269.69,2608.27 -4289.37,2588.58 -4360.24,2588.58 -4360.24,2644.68 -4360.24,2706.69
NetC23_2 on L1-TOP "NETC23_2_L01_P589" (solid, pour order 589): -4504.92,2748.03 -4426.18,2748.03 -4412.4,2734.25 -4412.4,2608.27 -4432.09,2588.58 -4502.95,2588.58 -4502.95,2644.68 -4489.17,2658.46 -4489.17,2692.91 -4504.92,2708.66
+3.3V_TST on L1-TOP "+3.3V_TST_L01_P572" (solid, pour order 572): 99.2,2983.17 461.4,2983.17 461.4,3031.39 475.18,3045.17 475.18,3105.21 446.64,3133.76 197.62,3133.76 181.87,3118.01 181.87,3069.78 157.27,3045.17 112.98,3045.17 99.2,3031.39
+3.3V_TST on L3-PWR "+3.3V_TST_L03_P587" (solid, remove dead copper, pour order 587): -5708.66,5708.66 2559.05,5708.66 2559.05,0 -5708.66,0
+5V_TST on L3-PWR "+5V_TST_L03_P564" (solid, pour order 564): -4133.86,5462.6 -4074.41,5462.6 -3838.19,5226.38 -2529.53,5226.38 -2293.31,5462.6 -2234.25,5462.6 -1998.03,5226.38 -590.55,5226.38 -354.33,5462.6 -305.12,5462.6 -68.9,5226.38 1259.84,5226.38 1496.06,5462.6 1545.28,5462.6 1643.7,5364.17 1643.7,4360.24 2137.8,3866.14 2303.15,3866.14 2303.15,3799.21 2204.72,3700.79 1564.96,3700.79 816.93,4448.82 -3921.26,4448.82 -4143.7,4226.38 -4143.7,4062.99 -4665.35,4062.99 -4665.35,4931.1
+1.8V on L3-PWR "+1.8V_L03_P586" (solid, pour order 586): -509.12,1570.87 -15.75,1570.87 311.02,1897.64 866.8,1897.64 909.45,1854.99 909.45,1318.9 905.51,1318.9 696.85,1110.24 696.85,744.09 547.24,594.49 -3212.6,594.49 -3389.76,771.65 -3574.8,771.65 -3618.11,728.35 -3618.11,0 657.48,0 2559.06,0 2559.06,2992.13 1677.17,2992.13 1374.02,3295.28 669.29,3295.28 606.3,3232.28 606.3,2968.5 902.22,2968.5 906.63,2964.09 906.63,2196.56 867.55,2157.48 -204.72,2157.48 -512.78,1849.42
FT232_VCCD on L3-PWR "FT232_VCCD_L03_P563" (solid, pour order 563): 1952.76,1047.24 2039.37,960.63 2039.37,366.14 2007.87,334.65 1464.57,334.65 1267.72,531.5 1267.72,909.45 1405.51,1047.24
NetC92_2 on L3-PWR "NETC92_2_L03_P570" (solid, pour order 570): 756.69,1544.68 892.5,1544.68 892.5,1856.64 859.28,1889.87 485.16,1889.87 324.61,1889.87 6.68,1571.94 6.68,1141.73 176.96,1141.73 176.96,1410.52 382.75,1616.3 706.49,1616.3 756.69,1566.1
NetC94_2 on L3-PWR "NETC94_2_L03_P571" (solid, pour order 571): 752.48,1529.52 892.5,1529.52 892.5,1339.35 694.88,1141.73 381.68,1141.73 381.68,1321.82 589.38,1529.52
NetC15_2 on L3-PWR "NETC15_2_L03_P584" (solid, pour order 584): -5055.12,2653.54 -5055.12,1555.12 -4551.18,1051.18 -4106.3,1051.18 -4047.24,992.13 -3893.7,992.13 -3893.79,992.21 -3893.79,1049.82 -3793.92,1049.82 -3767.72,1023.62 -3767.72,850.39 -3826.77,791.34 -4814.96,791.34 -5346.46,1322.83 -5346.46,2653.54
NetC17_2 on L3-PWR "NETC17_2_L03_P582" (solid, pour order 582): -4870.08,2653.54 -4870.08,1826.77 -4291.34,1248.03 -4094.49,1248.03 -3905.51,1059.06 -3905.51,1003.94 -4031.5,1003.94 -4094.49,1066.93 -4543.31,1066.93 -5039.37,1562.99 -5039.37,2653.54
NetC23_2 on L3-PWR "NETC23_2_L03_P579" (solid, pour order 579): -4405.51,2653.54 -4405.51,2188.98 -4251.97,2035.43 -4106.3,2035.43 -4047.24,1976.38 -3893.7,1976.38 -3893.79,1976.47 -3893.79,2034.07 -3793.92,2034.07 -3767.72,2007.87 -3767.72,1913.39 -3826.77,1854.33 -4350.39,1854.33 -4622.05,2125.98 -4622.05,2653.54
NetC25_2 on L3-PWR "NETC25_2_L03_P577" (solid, pour order 577): -4244.09,2653.54 -4244.09,2232.28 -4094.49,2232.28 -3905.51,2043.31 -3905.51,1988.19 -4031.5,1988.19 -4094.49,2051.18 -4244.09,2051.18 -4393.7,2200.79 -4393.7,2653.54
NetC106_2 on L3-PWR "NETC106_2_L03_P568" (solid, pour order 568): 757.69,2519.91 757.69,2442.79 397.47,2442.79 187.79,2652.47 187.79,2956.59 368.89,2956.59 368.89,2732.18 581.15,2519.91
NetC102_2 on L3-PWR "NETC102_2_L03_P567" (solid, pour order 567): 752.48,2529.53 752.48,2585.09 892.5,2585.09 892.5,2956.59 381.68,2956.59 381.68,2737.23 589.38,2529.53
NetC90_2 on L3-PWR "NETC90_2_L03_P573" (solid, pour order 573): 757.69,1539.14 757.69,1616.27 397.47,1616.27 187.79,1406.58 187.79,1141.73 368.89,1141.73 368.89,1326.88 581.15,1539.14
NetC13_2 on L3-PWR "NETC13_2_L03_P580" (solid, pour order 580): -4858.27,2653.54 -4641.73,2653.54 -4641.73,2122.05 -4358.27,1838.58 -4204.72,1838.58 -3791.34,1425.2 -3791.34,1059.06 -3885.83,1059.06 -4086.61,1259.84 -4279.53,1259.84 -4858.27,1838.58
NetC21_2 on L3-PWR "NETC21_2_L03_P575" (solid, pour order 575): -4232.28,2653.54 -4019.68,2653.54 -3787.4,2421.26 -3787.4,2043.31 -3881.89,2043.31 -4082.68,2244.09 -4232.28,2244.09
NetC104_2 on L3-PWR "NETC104_2_L03_P565" (solid, pour order 565): 756.69,2574.09 892.5,2574.09 892.5,2202.42 859.28,2169.19 485.16,2169.19 6.68,2169.19 6.68,2956.59 176.96,2956.59 176.96,2648.54 382.75,2442.75 706.49,2442.75 756.69,2492.95
DGND on L4-PWR "DGND_L04_P588" (solid, remove dead copper, pour order 588): -5708.66,5708.66 2559.05,5708.66 2559.05,0 -5708.66,0
VCCO_67_68_69 on L4-PWR "VCCO_67_68_69_L04_P583" (solid, remove dead copper, pour order 583): -4763.78,5708.66 -1909.45,5708.66 -1909.45,4596.46 -2439.49,4066.41 -2439.49,3907.48 -2500,3907.48 -3474.41,4881.89 -4566.93,4881.89 -4763.78,5078.74
+VDCIN on L4-PWR "+VDCIN_L04_P581" (solid, remove dead copper, pour order 581): -5295.28,5070.87 -4791.34,5070.87 -4582.68,4862.2 -3437.43,4862.2 -3397.64,4822.41 -3397.64,4795.28 68.9,1328.74 68.9,1092.52 19.68,1043.31 -1188.98,1043.31 -3511.81,3366.14 -5287.4,3366.14 -5364.17,3442.91 -5364.17,5001.97
NetC60_2 on L4-PWR "NETC60_2_L04_P574" (solid, pour order 574): 1625.98,606.3 1692.91,606.3 1714.96,584.25 1714.96,490.55 1704.72,480.31 1622.05,480.31 1598.43,503.94 1598.43,582.68
NetC9_2 on L4-PWR "NETC9_2_L04_P576" (solid, pour order 576): 1743.6,601.87 1804.15,601.87 1838.62,567.4 1838.58,567.36 1838.58,507.87 1811.02,480.31 1740.16,480.31 1732.28,488.19 1732.28,590.55
FT232_VREGIN on L4-PWR "FT232_VREGIN_L04_P578" (solid, pour order 578): 1417.32,880.87 1427.49,891.04 1490.85,891.04 1539.37,842.52 1539.37,799.21 1512.27,772.11 1440.94,772.11 1417.32,795.73
VCCO_64_66 on L4-PWR "VCCO_64_66_L04_P585" (solid, remove dead copper, pour order 585): -2423.57,4067.23 -1889.76,4601.03 -1889.76,5708.66 2559.06,5708.66 2559.06,4374.02 -734.25,4374.02 -1200.79,3907.48 -2423.57,3907.48
DGND on L6-BOT "DGND_L06_P604" (solid, pour order 604): -4921.26,5007.87 -4488.19,5007.87 -3940.94,4460.63 -3940.94,3559.06 -4385.83,3114.17 -4925.2,3114.17 -5157.48,3346.46 -5157.48,4771.65
DGND on L5-GND "L3_DGND" (solid, pour order 566): -5708.66,0 -5708.66,5708.66 2559.06,5708.66 2559.06,0
DGND on L2-GND "L2_DGND" (solid, pour order 569): -5708.66,0 -5708.66,5708.66 2559.05,5708.66 2559.06,0

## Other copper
L1-TOP:
  region net VCCO_64_66: 2519.04,4397.85 2519.04,4429.85 2431.04,4429.85 2431.04,4397.85
  region net +5V_TST: 2205.37,3857.17 2205.37,3825.17 2293.37,3825.17 2293.37,3857.17
  region net +3.3V_TST: 2293.06,4397.85 2293.06,4429.85 2205.06,4429.85 2205.06,4397.85
  region net +5V_TST: -4291.25,4074.87 -4659.25,4074.87 -4659.25,4232.87 -4291.25,4232.87
  region net +VDCIN: -4720.25,4572.87 -4720.25,4463.87 -4688.98,4463.87 -4688.98,4412.4 -4624.02,4412.4 -4624.02,4572.87
  region net DGND: -4711.29,4393.38 -4616.25,4393.38 -4616.25,4243.87 -4663.39,4243.87 -4663.39,4298.87 -4711.29,4298.87
  region net NetC53_2: -4291.25,4446.87 -4518.25,4446.87 -4518.25,4427.87 -4574.45,4371.67 -4608.42,4371.67 -4608.42,4306.71 -4291.25,4306.71
  region net +3.3V_TST: -4409.2,3512.06 -4409.2,3578.94 -4750.2,3578.94 -4750.2,3592.94 -4905.2,3592.94 -4905.2,3455.94 -4465.32,3455.94
  region net DGND: -4734.82,3594.96 -4290.87,3594.96 -4261.62,3624.2 -4261.62,3716.59 -4568.63,3716.59 -4577.29,3707.94 -4669.17,3707.94 -4669.17,3668.59 -4734.82,3668.59
  region net NetC39_2: -4681.38,3726.16 -4735.55,3726.16 -4740.81,3731.42 -4772.79,3731.42 -4772.79,3702.87 -4905.85,3702.87 -4905.85,3616.19 -4756.61,3616.19 -4756.61,3665.15 -4740.09,3681.67 -4681.38,3681.67
  region net +VDCIN: -4635.63,3736.59 -4635.63,3727.73 -4508.49,3727.73 -4501.63,3734.59 -4261.62,3734.59 -4261.62,3836.43 -4276.79,3851.59 -4506.55,3851.59 -4539.37,3818.77 -4539.37,3781.15 -4583.73,3736.79 -4635.37,3736.79

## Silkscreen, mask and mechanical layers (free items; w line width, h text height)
Top Overlay:
  circle w22: c-5476.38,4606.3 r11
  rectangle: 238.19,4370.08 988.19,4685.04
  lines w4.72: -3346.46,39.37 -3346.46,4724.41 0,4724.41 0,39.37
  lines w15.75: -5538.38,4606.3 -5476.38,4606.3 ; -5490.06,4568.71 ccw(c-5476.38,4606.3) -5490.06,4643.89 ; -5436.38,4606.3 -5388.38,4606.3
  text "DGND" at 1008,5078.87 h40
  text "-" at -5296.39,4641.29 h70 r180
  text "+" at -5551.38,4567.3 h70 r90
  text "+6 to +18 VDC" at -5641.6,4389.76 h90
  text "'.Part_Number' / '.PCB_Revision'XX" at 1513.93,4377.15 h40
  text "ON" at -5621.92,3614.3 h40
  text "XEM8370 POWER ENABLE" at -5434.03,3593.03 h90 r270
  text "226 REFCLK0" at 365.02,3292.17 h60
  text "225 REFCLK0" at 774.47,3292.17 h60
  text "228 REFCLK0" at 1185.66,3292.17 h60
  text "227 REFCLK0" at 1593.37,3292.17 h60
  text "OFF" at -5621.92,3177.29 h40
  text "3V3" at 1606.3,3059.06 h40
  text "130 REFCLK0" at -5416.49,3044.42 h60 r270
  text "3V3" at -5622.05,2625.98 h40
  text "USB JTAG" at 893.7,1020.87 h100
  text "TESTING ONLY" at -2045.07,783.46 h60
  text "129 REFCLK0" at -3639.45,758.27 h60
  text "JTAG HEADER" at 2279.53,531.5 h60 r90
  text "DGND" at -5208.54,39.5 h40
  text "DGND" at 63.12,39.5 h40
Dimensions:
  text ":::" at -3433.07,5791.34 h50 r180
  text ":::" at 249.45,5744.97 h50
  text ":::" at 2594.49,4933.07 h50 r270
  text ":::" at -5748.03,4488.19 h50 r90
  text ":::" at -5748.03,2559.06 h50 r90
  text ":::" at 2629.92,696.85 h50 r90
  text ":::" at -3177.17,-51.18 h50 r180
  text ":::" at -86.61,-62.99 h50 r180
Outline:
  the board outline again, w7.87
Mechanical:
  lines w3.94: -3346.46,0 -3346.46,4724.41 0,4724.41 0,0 -3346.46,0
